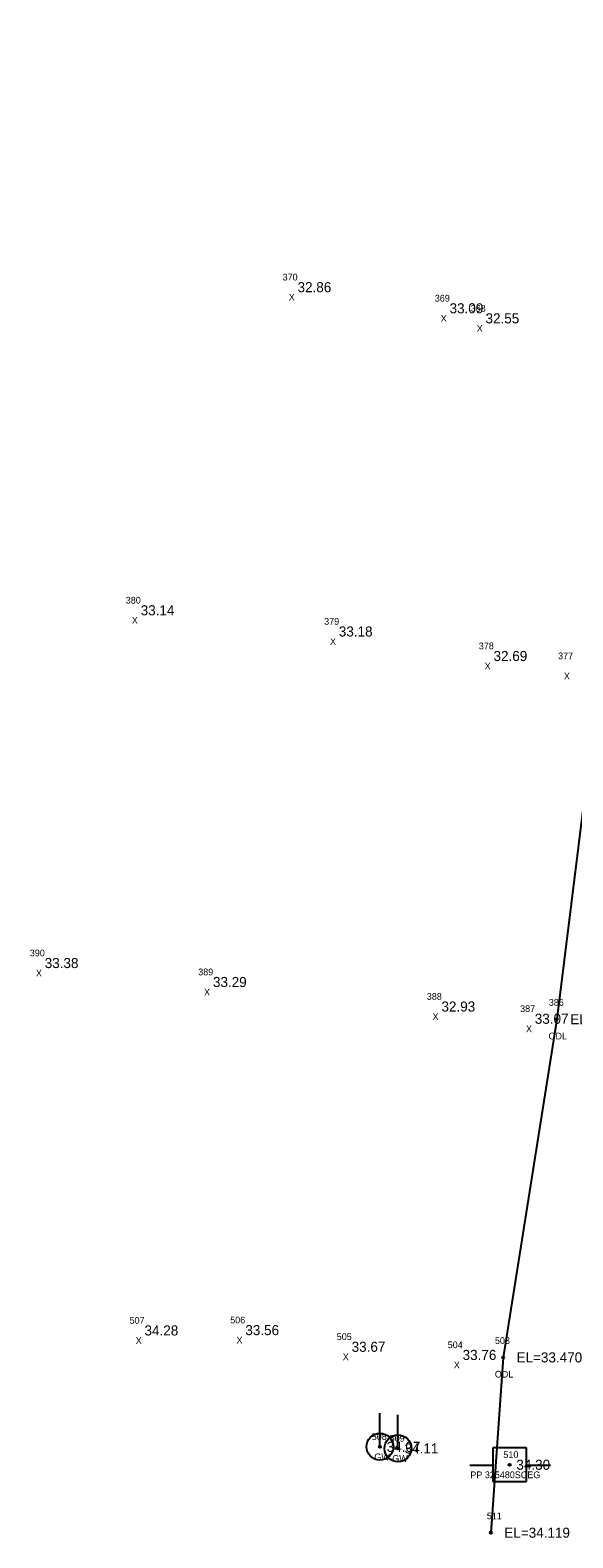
# Model space of a CAD drawing. Extents: x 2042117 to 2045853, y 303080 to 309569.
# Drawn here: x 2042739.2 to 2042820, y 307554 to 307778.3 of the extents above; entities that cross this region are included whole.
import ezdxf

# ---------------------------------------------------------------- set-up
doc = ezdxf.new("R2010")
doc.units = 0
for name, color, linetype in [('RD_EX_H2O', 7, 'Continuous'), ('RD_EX_H2O_txCode', 7, 'Continuous'), ('RD_EX_Misc_txCode', 7, 'Continuous'), ('RD_EX_TX_H2O_ELEV', 7, 'Continuous'), ('RD_EX_TX_Misc_ELEV', 7, 'Continuous'), ('RD_EX_TX_UT_ELEV', 7, 'Continuous'), ('RD_EX_UT', 7, 'Continuous'), ('RD_EX_UT_txCode', 7, 'Continuous'), ('RD_HC_Survey_ELEV', 7, 'Continuous'), ('RD_SMD_Locator', 7, 'Continuous')]:
    doc.layers.add(name, color=color, linetype=linetype)

msp = doc.modelspace()

# ---------------------------------------------------------------- linework, layer by layer
at = {"layer": 'RD_EX_H2O'}
msp.add_lwpolyline([(2043129.27, 308428.82), (2043103.11, 308386.53), (2043087.59, 308358.52), (2043078.21, 308342.14), (2043052.09, 308299.16), (2043025.98, 308255.36), (2043015.05, 308240.46), (2043007.57, 308236.11), (2042996.98, 308213.48), (2042981.31, 308163.04), (2042956.15, 308118.86), (2042936.41, 308071.81), (2042918.77, 308024.43), (2042903.29, 307975.96), (2042886.4, 307928.42), (2042872.04, 307879.53), (2042857.18, 307831.23), (2042843.33, 307782.22), (2042831.48, 307730.99), (2042823.97, 307682.68), (2042817.59, 307631.17), (2042809.6, 307580.86), (2042807.78, 307554.78)], dxfattribs=at)
at = {"layer": 'RD_EX_UT'}
for p, q in [((2042791.27, 307567.56), (2042791.27, 307572.56)), ((2042793.94, 307567.32), (2042793.94, 307572.32)), ((2042813.06, 307567.4), (2042808.06, 307567.4)), ((2042808.06, 307567.4), (2042808.06, 307562.4)), ((2042813.06, 307562.4), (2042813.06, 307567.4)), ((2042804.63, 307564.83), (2042808.1, 307564.83)), ((2042812.99, 307564.83), (2042816.63, 307564.83)), ((2042808.06, 307562.4), (2042813.06, 307562.4))]:
    msp.add_line(p, q, dxfattribs=at)
for centre in [(2042791.27, 307567.56), (2042793.94, 307567.32)]:
    msp.add_circle(centre, 2, dxfattribs=at)
at = {"layer": 'RD_SMD_Locator'}
for centre in [(2042817.59, 307631.17), (2042809.6, 307580.86), (2042791.27, 307567.56), (2042793.94, 307567.32), (2042810.57, 307564.89), (2042807.78, 307554.78)]:
    msp.add_circle(centre, 0.15, dxfattribs=at)

# ---------------------------------------------------------------- texts
at = {"layer": 'RD_EX_H2O_txCode'}
for s, p in [('386', (2042816.39, 307633.17)), ('ODL', (2042816.35, 307628.17)), ('503', (2042808.38, 307582.86)), ('ODL', (2042808.36, 307577.86)), ('511', (2042807.17, 307556.78))]:
    msp.add_text(s, height=1, dxfattribs=at).set_placement(p)
at = {"layer": 'RD_EX_Misc_txCode'}
for s, p in [('370', (2042776.79, 307741.08)), ('X', (2042777.7, 307738.08)), ('369', (2042799.43, 307737.94)), ('X', (2042800.32, 307734.94)), ('368', (2042804.78, 307736.44)), ('X', (2042805.67, 307733.44)), ('380', (2042753.45, 307693.01)), ('X', (2042754.35, 307690.01)), ('379', (2042782.97, 307689.86)), ('X', (2042783.84, 307686.86)), ('378', (2042805.98, 307686.21)), ('X', (2042806.85, 307683.21)), ('377', (2042817.78, 307684.73)), ('X', (2042818.64, 307681.73)), ('390', (2042739.17, 307640.53)), ('X', (2042740.08, 307637.53)), ('389', (2042764.23, 307637.71)), ('X', (2042765.1, 307634.71)), ('388', (2042798.24, 307634.06)), ('387', (2042812.13, 307632.24)), ('X', (2042799.1, 307631.06)), ('X', (2042813, 307629.24)), ('507', (2042754.02, 307585.87)), ('506', (2042768.99, 307585.92)), ('X', (2042754.93, 307582.87)), ('X', (2042769.92, 307582.92)), ('505', (2042784.84, 307583.44)), ('504', (2042801.35, 307582.23)), ('X', (2042785.74, 307580.44)), ('X', (2042802.26, 307579.23))]:
    msp.add_text(s, height=1, dxfattribs=at).set_placement(p)
at = {"layer": 'RD_EX_TX_H2O_ELEV'}
for s, p in [('EL=32.972', (2042819.59, 307630.42)), ('EL=33.470', (2042811.6, 307580.11)), ('EL=34.119', (2042809.78, 307554.03))]:
    msp.add_text(s, height=1.5, dxfattribs=at).set_placement(p)
at = {"layer": 'RD_EX_TX_Misc_ELEV'}
for s, p in [('32.86', (2042779.01, 307739.33)), ('33.09', (2042801.63, 307736.19)), ('32.55', (2042806.98, 307734.69)), ('33.14', (2042755.67, 307691.26)), ('33.18', (2042785.15, 307688.11)), ('32.69', (2042808.17, 307684.46)), ('33.38', (2042741.39, 307638.78)), ('33.29', (2042766.42, 307635.96)), ('32.93', (2042800.42, 307632.31)), ('33.07', (2042814.31, 307630.49)), ('34.28', (2042756.24, 307584.12)), ('33.56', (2042771.24, 307584.17)), ('33.67', (2042787.06, 307581.69)), ('33.76', (2042803.57, 307580.48))]:
    msp.add_text(s, height=1.5, dxfattribs=at).set_placement(p)
at = {"layer": 'RD_EX_TX_UT_ELEV'}
for s, p in [('34.07', (2042792.27, 307566.81)), ('34.11', (2042794.94, 307566.57))]:
    msp.add_text(s, height=1.5, dxfattribs=at).set_placement(p)
at = {"layer": 'RD_EX_UT_txCode'}
for s, p in [('508', (2042790.05, 307568.56)), ('509', (2042792.72, 307568.32)), ('GW', (2042790.43, 307565.56)), ('GW', (2042793.1, 307565.32)), ('510', (2042809.63, 307565.89)), ('PP 325480SCEG', (2042804.72, 307562.89))]:
    msp.add_text(s, height=1, dxfattribs=at).set_placement(p)
at = {"layer": 'RD_HC_Survey_ELEV'}
msp.add_text('34.30', height=1.5, dxfattribs=at).set_placement((2042811.57, 307564.14))

doc.saveas('drawing.dxf')
